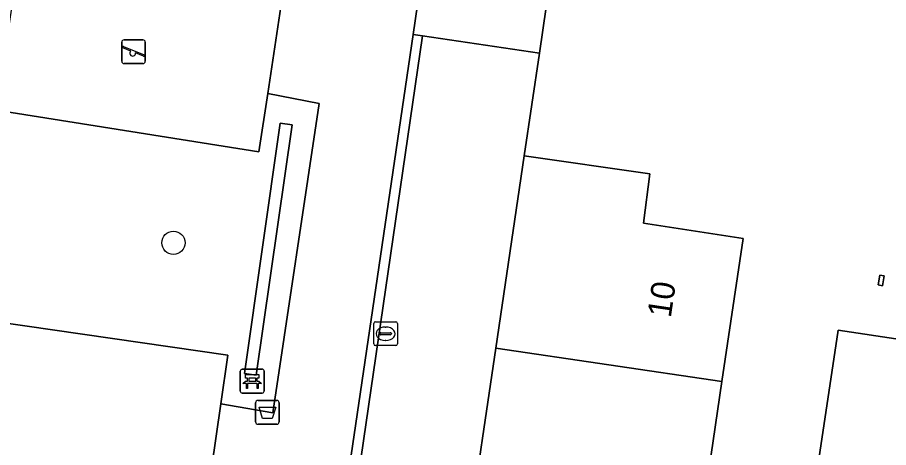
# Model space of a CAD drawing. Extents: x 164148 to 165261, y 382513 to 383432.
# Drawn here: x 164492.62 to 164529.26, y 383135.73 to 383153.8 of the extents above; entities that cross this region are included whole.
import ezdxf

# ---------------------------------------------------------------- set-up
doc = ezdxf.new("R2010")
doc.units = 0
for name, color, linetype in [('IMGEO_Afvalbak', 7, 'Continuous'), ('IMGEO_Bank', 7, 'Continuous'), ('IMGEO_Boom', 7, 'Continuous'), ('IMGEO_Erf', 7, 'Continuous'), ('IMGEO_Groenvoorziening', 7, 'Continuous'), ('IMGEO_Haag', 7, 'Continuous'), ('IMGEO_Kolk', 7, 'Continuous'), ('IMGEO_Muur', 7, 'Continuous'), ('IMGEO_Pand', 7, 'Continuous'), ('IMGEO_Pand_nummerreeks', 7, 'Continuous'), ('IMGEO_Rijbaan_lokaal_open', 7, 'Continuous'), ('IMGEO_Speelvoorziening', 7, 'Continuous'), ('IMGEO_Terreindeel_zand', 7, 'Continuous'), ('IMGEO_Voetpad_gesloten', 7, 'Continuous'), ('IMGEO_Voetpad_halfverhard', 7, 'Continuous')]:
    doc.layers.add(name, color=color, linetype=linetype)

msp = doc.modelspace()

# ---------------------------------------------------------------- linework, layer by layer
at = {"layer": 'IMGEO_Afvalbak'}
for p, q in [((164502.743, 383137.708), (164503.533, 383137.708)), ((164503.533, 383137.708), (164502.743, 383137.708)), ((164502.643, 383136.808), (164502.643, 383137.608)), ((164502.643, 383137.608), (164502.643, 383136.808)), ((164503.633, 383137.608), (164503.633, 383136.808)), ((164503.633, 383136.808), (164503.633, 383137.608)), ((164503.533, 383136.708), (164502.743, 383136.708)), ((164502.743, 383136.708), (164503.533, 383136.708))]:
    msp.add_line(p, q, dxfattribs=at)
msp.add_lwpolyline([(164502.786, 383137.422), (164503.49, 383137.422), (164503.341, 383136.952), (164502.935, 383136.952), (164502.786, 383137.422)], dxfattribs=at)
for centre, start, end in [((164502.743, 383137.608), 90, 180), ((164502.743, 383137.608), 90, 180), ((164503.533, 383137.608), 0, 90), ((164503.533, 383137.608), 360, 90), ((164502.743, 383136.808), 180, 270), ((164502.743, 383136.808), 180, 270), ((164503.533, 383136.808), 270, 0), ((164503.533, 383136.808), 270, 0)]:
    msp.add_arc(centre, 0.1, start, end, dxfattribs=at)
at = {"layer": 'IMGEO_Bank'}
for p, q in [((164501.999, 383138.093), (164501.999, 383138.934)), ((164501.999, 383138.934), (164501.999, 383138.093)), ((164502.074, 383139.018), (164502.915, 383139.018)), ((164502.915, 383139.018), (164502.074, 383139.018)), ((164502.999, 383138.943), (164502.999, 383138.102)), ((164502.999, 383138.102), (164502.999, 383138.943)), ((164502.308, 383138.524), (164502.308, 383138.63)), ((164502.352, 383138.63), (164502.352, 383138.524)), ((164502.64, 383138.636), (164502.358, 383138.636)), ((164502.358, 383138.518), (164502.64, 383138.518)), ((164502.646, 383138.524), (164502.646, 383138.63)), ((164502.69, 383138.63), (164502.69, 383138.524)), ((164502.696, 383138.416), (164502.303, 383138.416)), ((164502.924, 383138.018), (164502.083, 383138.018)), ((164502.083, 383138.018), (164502.924, 383138.018))]:
    msp.add_line(p, q, dxfattribs=at)
for points in [[(164502.302, 383138.636), (164502.216, 383138.636), (164502.216, 383138.797), (164502.779, 383138.797), (164502.779, 383138.636), (164502.696, 383138.636)], [(164502.246, 383138.416), (164502.104, 383138.416), (164502.216, 383138.518), (164502.302, 383138.518)], [(164502.696, 383138.518), (164502.779, 383138.518), (164502.891, 383138.416), (164502.752, 383138.416)], [(164502.296, 383138.409), (164502.296, 383138.202), (164502.253, 383138.202), (164502.253, 383138.409)], [(164502.746, 383138.409), (164502.746, 383138.202), (164502.702, 383138.202), (164502.702, 383138.409)]]:
    msp.add_lwpolyline(points, dxfattribs=at)
for centre, radius, start, end in [((164502.077, 383138.94), 0.0779, 92.4484, 184.2845), ((164502.077, 383138.94), 0.0779, 92.4484, 184.2845), ((164502.921, 383138.94), 0.0779, 2.4484, 94.2845), ((164502.921, 383138.94), 0.0779, 2.4484, 94.2845), ((164502.301, 383138.629), 0.00671, 2.8957, 87.1043), ((164502.301, 383138.525), 0.00671, 272.8957, 357.1043), ((164502.358, 383138.629), 0.00671, 92.8957, 177.1043), ((164502.358, 383138.525), 0.00671, 182.8957, 267.1043), ((164502.64, 383138.629), 0.00671, 2.8957, 87.1043), ((164502.64, 383138.525), 0.00671, 272.8957, 357.1043), ((164502.697, 383138.629), 0.00671, 92.8957, 177.1043), ((164502.697, 383138.525), 0.00671, 182.8957, 267.1043), ((164502.077, 383138.096), 0.0779, 182.4484, 274.2845), ((164502.077, 383138.096), 0.0779, 182.4484, 274.2845), ((164502.246, 383138.409), 0.00671, 2.8957, 87.1043), ((164502.303, 383138.409), 0.00671, 92.8957, 177.1043), ((164502.695, 383138.409), 0.00671, 2.8957, 87.1043), ((164502.752, 383138.409), 0.00671, 92.8957, 177.1043), ((164502.921, 383138.096), 0.0779, 272.4484, 4.2845), ((164502.921, 383138.096), 0.0779, 272.4484, 4.2845)]:
    msp.add_arc(centre, radius, start, end, dxfattribs=at)
at = {"layer": 'IMGEO_Boom'}
msp.add_circle((164499.185, 383144.33), 0.489, dxfattribs=at)
at = {"layer": 'IMGEO_Erf'}
for points in [[(164519.048, 383182.465), (164517.895, 383174.707), (164522.543, 383173.993), (164522.828, 383175.849), (164527.622, 383175.113), (164527.023, 383171.211), (164527.109, 383171.198), (164526.238, 383165.217), (164525.062, 383157.145), (164515.497, 383158.557), (164514.861, 383154.235), (164514.577, 383152.304), (164513.94, 383147.98), (164519.222, 383147.222), (164518.957, 383145.16), (164523.146, 383144.513), (164522.257, 383138.496), (164521.069, 383130.446)], [(164526.293, 383134.964), (164527.137, 383140.654), (164535.828, 383139.363), (164535.688, 383138.427), (164552.227, 383136.096), (164552.31, 383136.657), (164555.635, 383159.039), (164539.093, 383161.443), (164538.96, 383160.529), (164530.262, 383161.777), (164531.104, 383167.445), (164539.748, 383166.116), (164539.635, 383165.19), (164556.188, 383162.793), (164556.281, 383163.419), (164557.619, 383172.404), (164557.66, 383172.918)]]:
    msp.add_lwpolyline(points, dxfattribs=at)
msp.add_lwpolyline([(164528.824, 383142.557), (164528.892, 383142.974), (164529.081, 383142.943), (164529.013, 383142.526)], close=True, dxfattribs=at)
at = {"layer": 'IMGEO_Groenvoorziening'}
for points in [[(164505.608, 383128.283), (164506.045, 383128.219), (164509.663, 383153.021), (164509.271, 383153.078)], [(164506.045, 383128.219), (164510.912, 383127.509), (164511.548, 383131.862), (164512.742, 383139.908), (164513.94, 383147.98), (164514.577, 383152.304), (164509.663, 383153.021)], [(164504.175, 383149.287), (164503.681, 383149.359), (164502.171, 383138.839), (164502.665, 383138.767)], [(164502.665, 383138.767), (164502.171, 383138.839), (164503.681, 383149.359), (164504.175, 383149.287)]]:
    msp.add_lwpolyline(points, close=True, dxfattribs=at)
msp.add_lwpolyline([(164490.503, 383141.194), (164501.479, 383139.604), (164501.175, 383137.563), (164503.371, 383137.18), (164505.315, 383150.188), (164503.159, 383150.601), (164502.776, 383148.15), (164491.735, 383149.899)], dxfattribs=at)
at = {"layer": 'IMGEO_Haag'}
for points in [[(164505.608, 383128.283), (164506.045, 383128.219), (164509.663, 383153.021), (164509.271, 383153.078)], [(164504.175, 383149.287), (164503.681, 383149.359), (164502.171, 383138.839), (164502.665, 383138.767)]]:
    msp.add_lwpolyline(points, close=True, dxfattribs=at)
at = {"layer": 'IMGEO_Kolk'}
for p, q in [((164507.683, 383141.01), (164508.535, 383141.01)), ((164507.608, 383140.084), (164507.608, 383140.936)), ((164508.096, 383140.79), (164508.121, 383140.79)), ((164508.609, 383140.936), (164508.609, 383140.084)), ((164507.867, 383140.504), (164507.867, 383140.516)), ((164508.305, 383140.467), (164507.907, 383140.467)), ((164507.91, 383140.553), (164508.308, 383140.553)), ((164508.351, 383140.516), (164508.351, 383140.504)), ((164508.535, 383140.01), (164507.683, 383140.01)), ((164508.119, 383140.23), (164508.094, 383140.23))]:
    msp.add_line(p, q, dxfattribs=at)
for points in [[(164507.683, 383141.01), (164508.535, 383141.01)], [(164507.608, 383140.084), (164507.608, 383140.936)], [(164508.609, 383140.936), (164508.609, 383140.084)], [(164508.535, 383140.01), (164507.683, 383140.01)]]:
    msp.add_lwpolyline(points, dxfattribs=at)
for centre, radius, start, end in [((164507.685, 383140.934), 0.0765, 91.552, 178.448), ((164507.685, 383140.934), 0.0765, 91.552, 178.448), ((164508.533, 383140.934), 0.0765, 1.552, 88.448), ((164508.533, 383140.934), 0.0765, 1.552, 88.448), ((164507.907, 383140.513), 0.0403, 85.8775, 175.7526), ((164507.904, 383140.503), 0.0366, 178.938, 274.7102), ((164508.308, 383140.51), 0.043, 264.8664, 352.4533), ((164508.312, 383140.515), 0.0386, 1.7309, 96.639), ((164507.685, 383140.086), 0.0765, 181.552, 268.448), ((164507.685, 383140.086), 0.0765, 181.552, 268.448), ((164508.533, 383140.086), 0.0765, 271.552, 358.448), ((164508.533, 383140.086), 0.0765, 271.552, 358.448)]:
    msp.add_arc(centre, radius, start, end, dxfattribs=at)
for centre, major_axis, ratio, start_param, end_param in [((164508.095, 383140.51), (-0.387, 0.002), 0.722429, 4.712389, 7.853982), ((164508.12, 383140.51), (-0.39, 0.002), 0.717154, 1.570796, 4.712389)]:
    msp.add_ellipse(centre, major_axis=major_axis, ratio=ratio, start_param=start_param, end_param=end_param, dxfattribs=at)
at = {"layer": 'IMGEO_Muur'}
for points in [[(164514.577, 383152.304), (164514.861, 383154.235)], [(164513.94, 383147.98), (164514.577, 383152.304)]]:
    msp.add_lwpolyline(points, dxfattribs=at)
at = {"layer": 'IMGEO_Pand'}
for points in [[(164522.257, 383138.496), (164523.146, 383144.513), (164518.957, 383145.16), (164519.222, 383147.222), (164513.94, 383147.98), (164512.742, 383139.908)], [(164528.824, 383142.557), (164529.013, 383142.526), (164529.081, 383142.943), (164528.892, 383142.974)], [(164522.257, 383138.496), (164512.742, 383139.908), (164511.548, 383131.862), (164521.069, 383130.446)]]:
    msp.add_lwpolyline(points, close=True, dxfattribs=at)
at = {"layer": 'IMGEO_Rijbaan_lokaal_open'}
msp.add_lwpolyline([(164551.681, 383132.307), (164552.227, 383136.096), (164535.688, 383138.427), (164535.828, 383139.363), (164527.137, 383140.654), (164526.293, 383134.964), (164535.003, 383133.703), (164535.127, 383134.626)], close=True, dxfattribs=at)
at = {"layer": 'IMGEO_Speelvoorziening'}
for p, q in [((164497.013, 383151.957), (164497.013, 383152.757)), ((164497.013, 383152.757), (164497.013, 383151.957)), ((164497.113, 383152.857), (164497.903, 383152.857)), ((164497.903, 383152.857), (164497.113, 383152.857)), ((164498.003, 383152.757), (164498.003, 383151.957)), ((164498.003, 383151.957), (164498.003, 383152.757)), ((164497.396, 383152.385), (164497.057, 383152.522)), ((164497.082, 383152.582), (164497.958, 383152.229)), ((164497.934, 383152.169), (164497.594, 383152.306)), ((164497.903, 383151.857), (164497.113, 383151.857)), ((164497.113, 383151.857), (164497.903, 383151.857))]:
    msp.add_line(p, q, dxfattribs=at)
for centre, radius, start, end in [((164497.113, 383152.757), 0.1, 90, 180), ((164497.113, 383152.757), 0.1, 90, 180), ((164497.903, 383152.757), 0.1, 0, 90), ((164497.903, 383152.757), 0.1, 360, 90), ((164497.07, 383152.552), 0.0327, 68.078, 248.078), ((164497.475, 383152.295), 0.12, 130.9928, 5.1632), ((164497.946, 383152.199), 0.0327, 248.078, 68.078), ((164497.113, 383151.957), 0.1, 180, 270), ((164497.113, 383151.957), 0.1, 180, 270), ((164497.903, 383151.957), 0.1, 270, 0), ((164497.903, 383151.957), 0.1, 270, 0)]:
    msp.add_arc(centre, radius, start, end, dxfattribs=at)
at = {"layer": 'IMGEO_Terreindeel_zand'}
for points in [[(164501.839, 383167.764), (164497.639, 383168.449), (164494.539, 383168.955), (164494.054, 383165.655), (164492.441, 383154.698), (164491.735, 383149.899), (164502.776, 383148.15), (164503.159, 383150.601), (164504.121, 383157.056), (164504.784, 383161.653), (164505.577, 383167.155)], [(164500.185, 383130.675), (164501.175, 383137.563), (164501.479, 383139.604), (164490.503, 383141.194), (164489.473, 383134.127), (164488.76, 383129.233), (164491.56, 383128.806), (164495.853, 383128.153), (164499.726, 383127.563), (164500.089, 383130.021)]]:
    msp.add_lwpolyline(points, close=True, dxfattribs=at)
at = {"layer": 'IMGEO_Voetpad_gesloten'}
msp.add_lwpolyline([(164491.665, 383033.898), (164491.71, 383034.202), (164493.699, 383047.666), (164493.959, 383049.428), (164497.447, 383073.037), (164497.73, 383074.954), (164501.393, 383099.746), (164501.656, 383101.529), (164505.343, 383126.485), (164505.608, 383128.283), (164509.271, 383153.078), (164509.556, 383155.009), (164513.815, 383183.84), (164510.374, 383184.352), (164506.288, 383156.657), (164504.121, 383157.056), (164503.159, 383150.601), (164505.315, 383150.188), (164503.371, 383137.18), (164501.175, 383137.563), (164500.185, 383130.675), (164502.37, 383130.298), (164489.692, 383044.763), (164488.159, 383034.419)], close=True, dxfattribs=at)
at = {"layer": 'IMGEO_Voetpad_halfverhard'}
msp.add_lwpolyline([(164514.861, 383154.235), (164510.019, 383154.941), (164509.556, 383155.009), (164509.271, 383153.078), (164509.663, 383153.021), (164514.577, 383152.304)], close=True, dxfattribs=at)

# ---------------------------------------------------------------- texts
at = {"layer": 'IMGEO_Pand_nummerreeks'}
msp.add_text('10', height=1, rotation=81.6004, dxfattribs=at).set_placement((164520.102, 383141.151))

doc.saveas('drawing.dxf')
